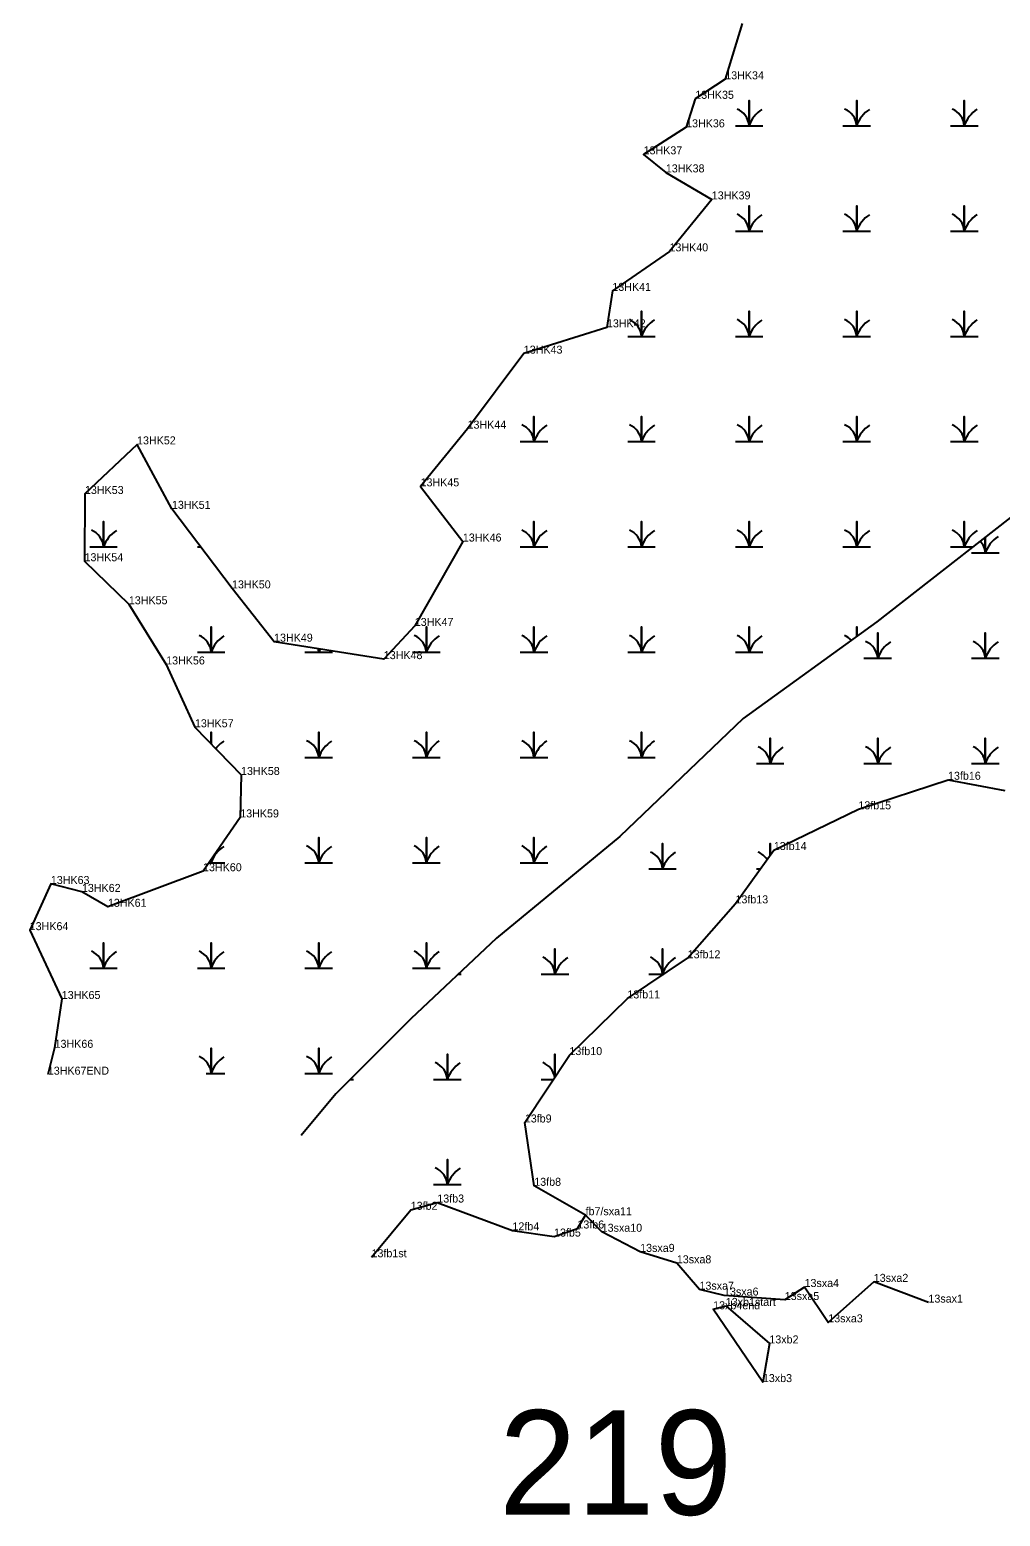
# Model space of a CAD drawing. Extents: x 2072529 to 2268796, y 436423 to 470406.
# Drawn here: x 2241127 to 2241734, y 449904 to 450833 of the extents above; entities that cross this region are included whole.
import ezdxf

# ---------------------------------------------------------------- set-up
doc = ezdxf.new("R2010")
doc.units = 0
for name, color, linetype in [('Default', 7, 'Continuous'), ('Exist Environmental Wetland Boundary', 7, 'Continuous'), ('Exist Environmental Wetland Boundary Cogo Comment', 7, 'Continuous'), ('Exist Hydro Jurisdictional Stream or Body of Water NEU Mitigable', 7, 'Continuous'), ('Exist Hydro Jurisdictional Stream or Body of Water NEU Mitigable Cogo Comment', 7, 'Continuous'), ('Exist Hydro Swamp or Marsh', 7, 'Continuous'), ('Old_Level_20', 7, 'Continuous')]:
    doc.layers.add(name, color=color, linetype=linetype)

msp = doc.modelspace()

# ---------------------------------------------------------------- linework, layer by layer
at = {"layer": 'Exist Environmental Wetland Boundary'}
for points in [[(2241572.42, 450837.03), (2241561.93, 450802.18), (2241543.17, 450789.99), (2241537.46, 450772.17), (2241510.89, 450755.29), (2241524.79, 450744), (2241553.51, 450727.12), (2241527.08, 450694.64), (2241491.36, 450669.95), (2241487.99, 450647.16), (2241436.01, 450630.74), (2241400.85, 450583.83), (2241371.5, 450547.78), (2241397.91, 450513.3), (2241367.85, 450460.53), (2241348.49, 450439.8), (2241279.92, 450450.71), (2241253.63, 450484.01), (2241216.08, 450533.73), (2241194.28, 450574.01), (2241161.72, 450543.02), (2241161.45, 450500.98), (2241189.14, 450474.08), (2241212.47, 450436.48), (2241230.46, 450397.2), (2241259.28, 450367.4), (2241258.78, 450340.87), (2241235.53, 450307.22), (2241176.05, 450285.01), (2241159.82, 450294.3), (2241140.39, 450299.26), (2241127.19, 450270.4), (2241147.21, 450227.38), (2241142.74, 450196.86), (2241138.49, 450180.09)], [(2241340.83, 450065.97), (2241365.31, 450095.64), (2241381.95, 450100.18), (2241428.92, 450082.79), (2241454.9, 450078.91), (2241469.52, 450083.95), (2241474.62, 450092.24), (2241442.55, 450110.62), (2241436.65, 450150.2), (2241464.53, 450192.33), (2241500.73, 450227.74), (2241538.43, 450252.82), (2241568.31, 450287.14), (2241592.29, 450320.48), (2241645.12, 450345.94), (2241701.17, 450364.41), (2241736.62, 450357.73)]]:
    msp.add_lwpolyline(points, dxfattribs=at)
msp.add_lwpolyline([(2241562.26, 450035.56), (2241589.5, 450012.12), (2241585.44, 449987.95), (2241554.37, 450033.47)], close=True, dxfattribs=at)
at = {"layer": 'Exist Hydro Jurisdictional Stream or Body of Water NEU Mitigable'}
for points in [[(2242125.2, 450828.12), (2242035.3, 450768.15), (2241988.4, 450717.87), (2241827.61, 450600.54), (2241763.96, 450546.9), (2241656.76, 450463.1), (2241573.02, 450402.76), (2241495.97, 450329.01), (2241418.92, 450265.32), (2241365.32, 450215.03), (2241318.42, 450168.1), (2241296.83, 450142.17)], [(2241688.94, 450037.62), (2241654.76, 450050.6), (2241626.3, 450025.29), (2241611.49, 450047.38), (2241599.12, 450039.26), (2241561.16, 450042.02), (2241545.82, 450045.72), (2241531.65, 450062.19), (2241508.73, 450069.34), (2241484.69, 450081.91), (2241474.62, 450092.24)]]:
    msp.add_lwpolyline(points, dxfattribs=at)
at = {"layer": 'Exist Hydro Swamp or Marsh'}
for points in [[(2241568.24, 450773.12), (2241576.84, 450773.12), (2241576.84, 450788.91), (2241576.84, 450773.12), (2241585.44, 450773.12)], [(2241635.49, 450773.12), (2241644.09, 450773.12), (2241644.09, 450788.91), (2241644.09, 450773.12), (2241652.69, 450773.12)], [(2241702.74, 450773.12), (2241711.34, 450773.12), (2241711.34, 450788.91), (2241711.34, 450773.12), (2241719.94, 450773.12)], [(2241568.24, 450707.32), (2241576.84, 450707.32), (2241576.84, 450723.11), (2241576.84, 450707.32), (2241585.44, 450707.32)], [(2241635.49, 450707.32), (2241644.09, 450707.32), (2241644.09, 450723.11), (2241644.09, 450707.32), (2241652.69, 450707.32)], [(2241702.74, 450707.32), (2241711.34, 450707.32), (2241711.34, 450723.11), (2241711.34, 450707.32), (2241719.94, 450707.32)], [(2241500.99, 450641.52), (2241509.59, 450641.52), (2241509.59, 450657.31), (2241509.59, 450641.52), (2241518.19, 450641.52)], [(2241568.24, 450641.52), (2241576.84, 450641.52), (2241576.84, 450657.31), (2241576.84, 450641.52), (2241585.44, 450641.52)], [(2241635.49, 450641.52), (2241644.09, 450641.52), (2241644.09, 450657.31), (2241644.09, 450641.52), (2241652.69, 450641.52)], [(2241702.74, 450641.52), (2241711.34, 450641.52), (2241711.34, 450657.31), (2241711.34, 450641.52), (2241719.94, 450641.52)], [(2241433.74, 450575.72), (2241442.34, 450575.72), (2241442.34, 450591.51), (2241442.34, 450575.72), (2241450.94, 450575.72)], [(2241500.99, 450575.72), (2241509.59, 450575.72), (2241509.59, 450591.51), (2241509.59, 450575.72), (2241518.19, 450575.72)], [(2241568.24, 450575.72), (2241576.84, 450575.72), (2241576.84, 450591.51), (2241576.84, 450575.72), (2241585.44, 450575.72)], [(2241635.49, 450575.72), (2241644.09, 450575.72), (2241644.09, 450591.51), (2241644.09, 450575.72), (2241652.69, 450575.72)], [(2241702.74, 450575.72), (2241711.34, 450575.72), (2241711.34, 450591.51), (2241711.34, 450575.72), (2241719.94, 450575.72)], [(2241164.74, 450509.92), (2241173.34, 450509.92), (2241173.34, 450525.71), (2241173.34, 450509.92), (2241181.94, 450509.92)], [(2241433.74, 450509.92), (2241442.34, 450509.92), (2241442.34, 450525.71), (2241442.34, 450509.92), (2241450.94, 450509.92)], [(2241500.99, 450509.92), (2241509.59, 450509.92), (2241509.59, 450525.71), (2241509.59, 450509.92), (2241518.19, 450509.92)], [(2241568.24, 450509.92), (2241576.84, 450509.92), (2241576.84, 450525.71), (2241576.84, 450509.92), (2241585.44, 450509.92)], [(2241635.49, 450509.92), (2241644.09, 450509.92), (2241644.09, 450525.71), (2241644.09, 450509.92), (2241652.69, 450509.92)], [(2241702.74, 450509.92), (2241711.34, 450509.92), (2241711.34, 450525.71), (2241711.34, 450509.92), (2241716.66, 450509.92)], [(2241231.99, 450509.92), (2241234.06, 450509.92)], [(2241715.88, 450506.16), (2241724.48, 450506.16), (2241724.48, 450516.04)], [(2241724.48, 450516.04), (2241724.48, 450506.16), (2241733.08, 450506.16)], [(2241231.99, 450444.12), (2241240.59, 450444.12), (2241240.59, 450459.91), (2241240.59, 450444.12), (2241249.19, 450444.12)], [(2241366.49, 450444.12), (2241375.09, 450444.12), (2241375.09, 450459.91), (2241375.09, 450444.12), (2241383.69, 450444.12)], [(2241433.74, 450444.12), (2241442.34, 450444.12), (2241442.34, 450459.91), (2241442.34, 450444.12), (2241450.94, 450444.12)], [(2241500.99, 450444.12), (2241509.59, 450444.12), (2241509.59, 450459.91), (2241509.59, 450444.12), (2241518.19, 450444.12)], [(2241568.24, 450444.12), (2241576.84, 450444.12), (2241576.84, 450459.91), (2241576.84, 450444.12), (2241585.44, 450444.12)], [(2241644.09, 450453.97), (2241644.09, 450459.91), (2241644.09, 450453.97)], [(2241648.63, 450440.36), (2241657.23, 450440.36), (2241657.23, 450456.14), (2241657.23, 450440.36), (2241665.83, 450440.36)], [(2241715.88, 450440.36), (2241724.48, 450440.36), (2241724.48, 450456.14), (2241724.48, 450440.36), (2241733.08, 450440.36)], [(2241299.24, 450444.12), (2241307.84, 450444.12), (2241307.84, 450446.27)], [(2241307.84, 450446.27), (2241307.84, 450444.12), (2241316.44, 450444.12)], [(2241240.59, 450386.72), (2241240.59, 450394.11), (2241240.59, 450386.72)], [(2241299.24, 450378.32), (2241307.84, 450378.32), (2241307.84, 450394.11), (2241307.84, 450378.32), (2241316.44, 450378.32)], [(2241366.49, 450378.32), (2241375.09, 450378.32), (2241375.09, 450394.11), (2241375.09, 450378.32), (2241383.69, 450378.32)], [(2241433.74, 450378.32), (2241442.34, 450378.32), (2241442.34, 450394.11), (2241442.34, 450378.32), (2241450.94, 450378.32)], [(2241500.99, 450378.32), (2241509.59, 450378.32), (2241509.59, 450394.11), (2241509.59, 450378.32), (2241518.19, 450378.32)], [(2241581.38, 450374.56), (2241589.98, 450374.56), (2241589.98, 450390.34), (2241589.98, 450374.56), (2241598.58, 450374.56)], [(2241648.63, 450374.56), (2241657.23, 450374.56), (2241657.23, 450390.34), (2241657.23, 450374.56), (2241665.83, 450374.56)], [(2241715.88, 450374.56), (2241724.48, 450374.56), (2241724.48, 450390.34), (2241724.48, 450374.56), (2241733.08, 450374.56)], [(2241248.71, 450378.32), (2241249.19, 450378.32)], [(2241299.24, 450312.52), (2241307.84, 450312.52), (2241307.84, 450328.31), (2241307.84, 450312.52), (2241316.44, 450312.52)], [(2241366.49, 450312.52), (2241375.09, 450312.52), (2241375.09, 450328.31), (2241375.09, 450312.52), (2241383.69, 450312.52)], [(2241433.74, 450312.52), (2241442.34, 450312.52), (2241442.34, 450328.31), (2241442.34, 450312.52), (2241450.94, 450312.52)], [(2241514.13, 450308.76), (2241522.73, 450308.76), (2241522.73, 450324.54), (2241522.73, 450308.76), (2241531.33, 450308.76)], [(2241589.98, 450317.28), (2241589.98, 450324.54), (2241589.98, 450317.28)], [(2241239.2, 450312.52), (2241240.59, 450312.52), (2241240.59, 450314.55)], [(2241240.59, 450314.55), (2241240.59, 450312.52), (2241249.19, 450312.52)], [(2241581.38, 450308.76), (2241583.85, 450308.76)], [(2241164.74, 450246.72), (2241173.34, 450246.72), (2241173.34, 450262.51), (2241173.34, 450246.72), (2241181.94, 450246.72)], [(2241231.99, 450246.72), (2241240.59, 450246.72), (2241240.59, 450262.51), (2241240.59, 450246.72), (2241249.19, 450246.72)], [(2241299.24, 450246.72), (2241307.84, 450246.72), (2241307.84, 450262.51), (2241307.84, 450246.72), (2241316.44, 450246.72)], [(2241366.49, 450246.72), (2241375.09, 450246.72), (2241375.09, 450262.51), (2241375.09, 450246.72), (2241383.69, 450246.72)], [(2241446.88, 450242.96), (2241455.48, 450242.96), (2241455.48, 450258.74), (2241455.48, 450242.96), (2241464.08, 450242.96)], [(2241514.13, 450242.96), (2241522.73, 450242.96), (2241522.73, 450258.74), (2241522.73, 450242.96), (2241523.6, 450242.96)], [(2241395.09, 450242.96), (2241396.83, 450242.96)], [(2241237.48, 450180.92), (2241240.59, 450180.92), (2241240.59, 450196.71), (2241240.59, 450180.92), (2241249.19, 450180.92)], [(2241299.24, 450180.92), (2241307.84, 450180.92), (2241307.84, 450196.71), (2241307.84, 450180.92), (2241316.44, 450180.92)], [(2241379.63, 450177.16), (2241388.23, 450177.16), (2241388.23, 450192.94), (2241388.23, 450177.16), (2241396.83, 450177.16)], [(2241455.48, 450178.66), (2241455.48, 450192.94), (2241455.48, 450178.66)], [(2241327.47, 450177.16), (2241329.58, 450177.16)], [(2241446.88, 450177.16), (2241454.49, 450177.16)], [(2241379.63, 450111.36), (2241388.23, 450111.36), (2241388.23, 450127.14), (2241388.23, 450111.36), (2241396.83, 450111.36)]]:
    msp.add_lwpolyline(points, dxfattribs=at)
for centre, radius, start, end in [((2241564.58, 450772.24), 12.3, 4.14034, 67.53497), ((2241595.08, 450767.06), 19.22, 122.12745, 161.62219), ((2241631.83, 450772.24), 12.3, 4.14034, 67.53497), ((2241662.33, 450767.06), 19.22, 122.12745, 161.62219), ((2241699.08, 450772.24), 12.3, 4.14034, 67.53497), ((2241729.58, 450767.06), 19.22, 122.12745, 161.62219), ((2241564.58, 450706.44), 12.3, 4.14034, 67.53497), ((2241595.08, 450701.26), 19.22, 122.12745, 161.62219), ((2241631.83, 450706.44), 12.3, 4.14034, 67.53497), ((2241662.33, 450701.26), 19.22, 122.12745, 161.62219), ((2241699.08, 450706.44), 12.3, 4.14034, 67.53497), ((2241729.58, 450701.26), 19.22, 122.12745, 161.62219), ((2241497.33, 450640.64), 12.3, 4.14034, 67.53497), ((2241527.83, 450635.46), 19.22, 122.12745, 161.62219), ((2241564.58, 450640.64), 12.3, 4.14034, 67.53497), ((2241595.08, 450635.46), 19.22, 122.12745, 161.62219), ((2241631.83, 450640.64), 12.3, 4.14034, 67.53497), ((2241662.33, 450635.46), 19.22, 122.12745, 161.62219), ((2241699.08, 450640.64), 12.3, 4.14034, 67.53497), ((2241729.58, 450635.46), 19.22, 122.12745, 161.62219), ((2241430.08, 450574.84), 12.3, 4.14034, 67.53497), ((2241460.58, 450569.66), 19.22, 122.12745, 161.62219), ((2241497.33, 450574.84), 12.3, 4.14034, 67.53497), ((2241527.83, 450569.66), 19.22, 122.12745, 161.62219), ((2241564.58, 450574.84), 12.3, 4.14034, 67.53497), ((2241595.08, 450569.66), 19.22, 122.12745, 161.62219), ((2241631.83, 450574.84), 12.3, 4.14034, 67.53497), ((2241662.33, 450569.66), 19.22, 122.12745, 161.62219), ((2241699.08, 450574.84), 12.3, 4.14034, 67.53497), ((2241729.58, 450569.66), 19.22, 122.12745, 161.62219), ((2241161.08, 450509.04), 12.3, 4.14034, 67.53497), ((2241191.58, 450503.86), 19.22, 122.12745, 161.62219), ((2241430.08, 450509.04), 12.3, 4.14034, 67.53497), ((2241460.58, 450503.86), 19.22, 122.12745, 161.62219), ((2241497.33, 450509.04), 12.3, 4.14034, 67.53497), ((2241527.83, 450503.86), 19.22, 122.12745, 161.62219), ((2241564.58, 450509.04), 12.3, 4.14034, 67.53497), ((2241595.08, 450503.86), 19.22, 122.12745, 161.62219), ((2241631.83, 450509.04), 12.3, 4.14034, 67.53497), ((2241662.33, 450503.86), 19.22, 122.12745, 161.62219), ((2241699.08, 450509.04), 12.3, 4.14034, 67.53497), ((2241729.58, 450503.86), 19.22, 122.12745, 161.62219), ((2241712.22, 450505.27), 12.3, 4.14034, 42.35219), ((2241742.72, 450500.1), 19.22, 122.12745, 161.62219), ((2241228.33, 450443.24), 12.3, 4.14034, 67.53497), ((2241258.83, 450438.06), 19.22, 122.12745, 161.62219), ((2241362.83, 450443.24), 12.3, 4.14034, 67.53497), ((2241393.33, 450438.06), 19.22, 122.12745, 161.62219), ((2241430.08, 450443.24), 12.3, 4.14034, 67.53497), ((2241460.58, 450438.06), 19.22, 122.12745, 161.62219), ((2241497.33, 450443.24), 12.3, 4.14034, 67.53497), ((2241527.83, 450438.06), 19.22, 122.12745, 161.62219), ((2241564.58, 450443.24), 12.3, 4.14034, 67.53497), ((2241595.08, 450438.06), 19.22, 122.12745, 161.62219), ((2241631.83, 450443.24), 12.3, 42.94561, 67.53497), ((2241295.58, 450443.24), 12.3, 4.14034, 14.55059), ((2241326.08, 450438.06), 19.22, 155.15226, 161.62219), ((2241644.97, 450439.47), 12.3, 4.14034, 67.53497), ((2241675.47, 450434.3), 19.22, 122.12745, 161.62219), ((2241712.22, 450439.47), 12.3, 4.14034, 67.53497), ((2241742.72, 450434.3), 19.22, 122.12745, 161.62219), ((2241295.58, 450377.44), 12.3, 4.14034, 67.53497), ((2241362.83, 450377.44), 12.3, 4.14034, 67.53497), ((2241430.08, 450377.44), 12.3, 4.14034, 67.53497), ((2241497.33, 450377.44), 12.3, 4.14034, 67.53497), ((2241258.83, 450372.26), 19.22, 122.12745, 143.21763), ((2241326.08, 450372.26), 19.22, 122.12745, 161.62219), ((2241393.33, 450372.26), 19.22, 122.12745, 161.62219), ((2241460.58, 450372.26), 19.22, 122.12745, 161.62219), ((2241527.83, 450372.26), 19.22, 122.12745, 161.62219), ((2241577.72, 450373.67), 12.3, 4.14034, 67.53497), ((2241608.22, 450368.5), 19.22, 122.12745, 161.62219), ((2241644.97, 450373.67), 12.3, 4.14034, 67.53497), ((2241675.47, 450368.5), 19.22, 122.12745, 161.62219), ((2241712.22, 450373.67), 12.3, 4.14034, 67.53497), ((2241742.72, 450368.5), 19.22, 122.12745, 161.62219), ((2241258.83, 450306.46), 19.22, 122.12745, 161.62219), ((2241295.58, 450311.64), 12.3, 4.14034, 67.53497), ((2241326.08, 450306.46), 19.22, 122.12745, 161.62219), ((2241362.83, 450311.64), 12.3, 4.14034, 67.53497), ((2241393.33, 450306.46), 19.22, 122.12745, 161.62219), ((2241430.08, 450311.64), 12.3, 4.14034, 67.53497), ((2241460.58, 450306.46), 19.22, 122.12745, 161.62219), ((2241510.47, 450307.87), 12.3, 4.14034, 67.53497), ((2241540.97, 450302.7), 19.22, 122.12745, 161.62219), ((2241577.72, 450307.87), 12.3, 32.99449, 67.53497), ((2241228.33, 450311.64), 12.3, 4.14034, 12.03866), ((2241161.08, 450245.84), 12.3, 4.14034, 67.53497), ((2241191.58, 450240.66), 19.22, 122.12745, 161.62219), ((2241228.33, 450245.84), 12.3, 4.14034, 67.53497), ((2241258.83, 450240.66), 19.22, 122.12745, 161.62219), ((2241295.58, 450245.84), 12.3, 4.14034, 67.53497), ((2241326.08, 450240.66), 19.22, 122.12745, 161.62219), ((2241362.83, 450245.84), 12.3, 4.14034, 67.53497), ((2241393.33, 450240.66), 19.22, 122.12745, 161.62219), ((2241443.22, 450242.07), 12.3, 4.14034, 67.53497), ((2241473.72, 450236.9), 19.22, 122.12745, 161.62219), ((2241510.47, 450242.07), 12.3, 4.14034, 67.53497), ((2241540.97, 450236.9), 19.22, 122.12745, 161.62219), ((2241228.33, 450180.04), 12.3, 4.14034, 67.53497), ((2241258.83, 450174.86), 19.22, 122.12745, 161.62219), ((2241295.58, 450180.04), 12.3, 4.14034, 67.53497), ((2241326.08, 450174.86), 19.22, 122.12745, 161.62219), ((2241375.97, 450176.27), 12.3, 4.14034, 67.53497), ((2241406.47, 450171.1), 19.22, 122.12745, 161.62219), ((2241443.22, 450176.27), 12.3, 10.07397, 67.53497), ((2241375.97, 450110.47), 12.3, 4.14034, 67.53497), ((2241406.47, 450105.3), 19.22, 122.12745, 161.62219)]:
    msp.add_arc(centre, radius, start, end, dxfattribs=at)
at = {"layer": 'Old_Level_20'}
for p, q in [((2241561.93, 450802.18), (2241561.93, 450802.18)), ((2241543.17, 450789.99), (2241543.17, 450789.99)), ((2241537.46, 450772.17), (2241537.46, 450772.17)), ((2241510.89, 450755.29), (2241510.89, 450755.29)), ((2241524.79, 450744), (2241524.79, 450744)), ((2241553.51, 450727.12), (2241553.51, 450727.12)), ((2241527.08, 450694.64), (2241527.08, 450694.64)), ((2241491.36, 450669.95), (2241491.36, 450669.95)), ((2241487.99, 450647.16), (2241487.99, 450647.16)), ((2241436.01, 450630.74), (2241436.01, 450630.74)), ((2241400.85, 450583.83), (2241400.85, 450583.83)), ((2241194.28, 450574.01), (2241194.28, 450574.01)), ((2241371.5, 450547.78), (2241371.5, 450547.78)), ((2241161.72, 450543.02), (2241161.72, 450543.02)), ((2241216.08, 450533.73), (2241216.08, 450533.73)), ((2241397.91, 450513.3), (2241397.91, 450513.3)), ((2241161.45, 450500.98), (2241161.45, 450500.98)), ((2241253.63, 450484.01), (2241253.63, 450484.01)), ((2241189.14, 450474.08), (2241189.14, 450474.08)), ((2241367.85, 450460.53), (2241367.85, 450460.53)), ((2241279.92, 450450.71), (2241279.92, 450450.71)), ((2241212.47, 450436.48), (2241212.47, 450436.48)), ((2241348.49, 450439.8), (2241348.49, 450439.8)), ((2241230.46, 450397.2), (2241230.46, 450397.2)), ((2241259.28, 450367.4), (2241259.28, 450367.4)), ((2241701.17, 450364.41), (2241701.17, 450364.41)), ((2241645.12, 450345.94), (2241645.12, 450345.94)), ((2241258.78, 450340.87), (2241258.78, 450340.87)), ((2241592.29, 450320.48), (2241592.29, 450320.48)), ((2241235.53, 450307.22), (2241235.53, 450307.22)), ((2241140.39, 450299.26), (2241140.39, 450299.26)), ((2241159.82, 450294.3), (2241159.82, 450294.3)), ((2241568.31, 450287.14), (2241568.31, 450287.14)), ((2241176.05, 450285.01), (2241176.05, 450285.01)), ((2241127.19, 450270.4), (2241127.19, 450270.4)), ((2241538.43, 450252.82), (2241538.43, 450252.82)), ((2241147.21, 450227.38), (2241147.21, 450227.38)), ((2241500.73, 450227.74), (2241500.73, 450227.74)), ((2241142.74, 450196.86), (2241142.74, 450196.86)), ((2241464.53, 450192.33), (2241464.53, 450192.33)), ((2241138.49, 450180.09), (2241138.49, 450180.09)), ((2241436.65, 450150.2), (2241436.65, 450150.2)), ((2241442.55, 450110.62), (2241442.55, 450110.62)), ((2241365.31, 450095.64), (2241365.31, 450095.64)), ((2241381.95, 450100.18), (2241381.95, 450100.18)), ((2241474.62, 450092.24), (2241474.62, 450092.24)), ((2241474.62, 450092.24), (2241474.62, 450092.24)), ((2241428.92, 450082.79), (2241428.92, 450082.79)), ((2241469.52, 450083.95), (2241469.52, 450083.95)), ((2241454.9, 450078.91), (2241454.9, 450078.91)), ((2241484.69, 450081.91), (2241484.69, 450081.91)), ((2241340.83, 450065.97), (2241340.83, 450065.97)), ((2241508.73, 450069.34), (2241508.73, 450069.34)), ((2241531.65, 450062.19), (2241531.65, 450062.19)), ((2241545.82, 450045.72), (2241545.82, 450045.72)), ((2241611.49, 450047.38), (2241611.49, 450047.38)), ((2241654.76, 450050.6), (2241654.76, 450050.6)), ((2241561.16, 450042.02), (2241561.16, 450042.02)), ((2241562.26, 450035.56), (2241562.26, 450035.56)), ((2241599.12, 450039.26), (2241599.12, 450039.26)), ((2241688.94, 450037.62), (2241688.94, 450037.62)), ((2241554.37, 450033.47), (2241554.37, 450033.47)), ((2241626.3, 450025.29), (2241626.3, 450025.29)), ((2241589.5, 450012.12), (2241589.5, 450012.12)), ((2241585.44, 449987.95), (2241585.44, 449987.95))]:
    msp.add_line(p, q, dxfattribs=at)

# ---------------------------------------------------------------- texts
at = {"layer": 'Default'}
msp.add_text('219', height=65.34, dxfattribs=at).set_placement((2241420.56, 449905.02))
at = {"layer": 'Exist Environmental Wetland Boundary Cogo Comment'}
for s, p in [('13HK34', (2241561.93, 450802.18)), ('13HK35', (2241543.17, 450789.99)), ('13HK36', (2241537.46, 450772.17)), ('13HK37', (2241510.89, 450755.29)), ('13HK38', (2241524.79, 450744)), ('13HK39', (2241553.51, 450727.12)), ('13HK40', (2241527.08, 450694.64)), ('13HK41', (2241491.36, 450669.95)), ('13HK42', (2241487.99, 450647.16)), ('13HK43', (2241436.01, 450630.74)), ('13HK44', (2241400.85, 450583.83)), ('13HK52', (2241194.28, 450574.01)), ('13HK53', (2241161.72, 450543.02)), ('13HK45', (2241371.5, 450547.78)), ('13HK51', (2241216.08, 450533.73)), ('13HK46', (2241397.91, 450513.3)), ('13HK54', (2241161.45, 450500.98)), ('13HK50', (2241253.63, 450484.01)), ('13HK55', (2241189.14, 450474.08)), ('13HK47', (2241367.85, 450460.53)), ('13HK49', (2241279.92, 450450.71)), ('13HK48', (2241348.49, 450439.8)), ('13HK56', (2241212.47, 450436.48)), ('13HK57', (2241230.46, 450397.2)), ('13HK58', (2241259.28, 450367.4)), ('13fb16', (2241701.17, 450364.41)), ('13HK59', (2241258.78, 450340.87)), ('13fb15', (2241645.12, 450345.94)), ('13fb14', (2241592.29, 450320.48)), ('13HK60', (2241235.53, 450307.22)), ('13HK63', (2241140.39, 450299.26)), ('13HK62', (2241159.82, 450294.3)), ('13HK61', (2241176.05, 450285.01)), ('13fb13', (2241568.31, 450287.14)), ('13HK64', (2241127.19, 450270.4)), ('13fb12', (2241538.43, 450252.82)), ('13HK65', (2241147.21, 450227.38)), ('13fb11', (2241500.73, 450227.74)), ('13HK66', (2241142.74, 450196.86)), ('13fb10', (2241464.53, 450192.33)), ('13HK67END', (2241138.49, 450180.09)), ('13fb9', (2241436.65, 450150.2)), ('13fb8', (2241442.55, 450110.62)), ('13fb2', (2241365.31, 450095.64)), ('13fb3', (2241381.95, 450100.18)), ('fb7/sxa11', (2241474.62, 450092.24)), ('12fb4', (2241428.92, 450082.79)), ('13fb5', (2241454.9, 450078.91)), ('13fb1st', (2241340.83, 450065.97))]:
    msp.add_text(s, height=5, dxfattribs=at).set_placement(p)
at = {"layer": 'Exist Hydro Jurisdictional Stream or Body of Water NEU Mitigable Cogo Comment'}
for s, p in [('13fb6', (2241469.52, 450083.95)), ('13sxa10', (2241484.69, 450081.91)), ('13sxa9', (2241508.73, 450069.34)), ('13sxa8', (2241531.65, 450062.19)), ('13sxa2', (2241654.76, 450050.6)), ('13sxa7', (2241545.82, 450045.72)), ('13sxa6', (2241561.16, 450042.02)), ('13sxa4', (2241611.49, 450047.38)), ('13xb4end', (2241554.37, 450033.47)), ('13xb1start', (2241562.26, 450035.56)), ('13sxa5', (2241599.12, 450039.26)), ('13sax1', (2241688.94, 450037.62)), ('13sxa3', (2241626.3, 450025.29)), ('13xb2', (2241589.5, 450012.12)), ('13xb3', (2241585.44, 449987.95))]:
    msp.add_text(s, height=5, dxfattribs=at).set_placement(p)

doc.saveas('drawing.dxf')
